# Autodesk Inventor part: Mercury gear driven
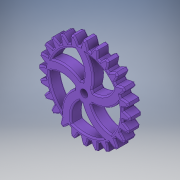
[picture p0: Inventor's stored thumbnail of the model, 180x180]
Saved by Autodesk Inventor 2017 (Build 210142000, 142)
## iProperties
Created: 2016-05
Part Number: Mercury gear driven
Material: Generic
Document SubType Name: Modeling
Designer: Stan
Density: 1 g/cm^3
Appearance: Violet
Author: Stan
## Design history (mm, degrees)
sketch "Sketch1"
  geometry: C1 r 1.984 at (0, 0); A1 r 13.958 centre (21.383, -4.97) between (13.573, -16.538) and (17.096, -18.253); A2 r 13.958 centre (21.383, -4.97) between (13.573, -16.538) and (17.096, -18.253); A3 r 13.958 centre (4.97, -21.383) between (18.253, -17.096) and (16.538, -13.573); A4 r 13.958 centre (4.97, -21.383) between (18.253, -17.096) and (16.538, -13.573); A5 r 13.958 centre (6.387, 21.003) between (-7.26, 23.932) and (-7.536, 20.023); A6 r 13.958 centre (-19.368, 10.335) between (-8.83, 19.488) and (-11.789, 22.056); A7 r 13.958 centre (0.734, 21.94) between (-13.207, 21.238) and (-12.462, 17.391); A8 r 13.958 centre (-21.383, 4.97) between (-13.573, 16.538) and (-17.096, 18.253); A9 r 13.958 centre (-4.97, 21.383) between (-18.253, 17.096) and (-16.538, 13.573); A10 r 13.958 centre (-21.94, -0.734) between (-17.391, 12.462) and (-21.238, 13.207); A11 r 13.958 centre (-10.335, 19.368) between (-22.056, 11.789) and (-19.488, 8.83); A12 r 13.958 centre (-21.003, -6.387) between (-20.023, 7.536) and (-23.932, 7.26); A13 r 13.958 centre (-14.995, 16.033) between (-24.356, 5.679) and (-21.109, 3.485); A14 r 13.958 centre (-18.634, -11.606) between (-21.292, 2.097) and (-24.996, 0.818); A15 r 13.958 centre (-18.634, 11.606) between (-24.996, -0.818) and (-21.292, -2.097); A16 r 13.958 centre (-14.995, -16.033) between (-21.109, -3.485) and (-24.356, -5.679); A17 r 13.958 centre (-21.003, 6.387) between (-23.932, -7.26) and (-20.023, -7.536); A18 r 13.958 centre (-10.335, -19.368) between (-19.488, -8.83) and (-22.056, -11.789); A19 r 13.958 centre (-21.94, 0.734) between (-21.238, -13.207) and (-17.391, -12.462); A20 r 13.958 centre (-4.97, -21.383) between (-16.538, -13.573) and (-18.253, -17.096); A21 r 13.958 centre (-21.383, -4.97) between (-17.096, -18.253) and (-13.573, -16.538); A22 r 13.958 centre (0.734, -21.94) between (-12.462, -17.391) and (-13.207, -21.238); A23 r 13.958 centre (-19.368, -10.335) between (-11.789, -22.056) and (-8.83, -19.488); A24 r 13.958 centre (6.387, -21.003) between (-7.536, -20.023) and (-7.26, -23.932); A25 r 13.958 centre (-16.033, -14.995) between (-5.679, -24.356) and (-3.485, -21.109); A26 r 13.958 centre (11.606, -18.634) between (-2.097, -21.292) and (-0.818, -24.996); A27 r 13.958 centre (-11.606, -18.634) between (0.818, -24.996) and (2.097, -21.292); A28 r 13.958 centre (16.033, -14.995) between (3.485, -21.109) and (5.679, -24.356); A29 r 13.958 centre (-6.387, -21.003) between (7.26, -23.932) and (7.536, -20.023); A30 r 13.958 centre (19.368, -10.335) between (8.83, -19.488) and (11.789, -22.056); A31 r 13.958 centre (-0.734, -21.94) between (13.207, -21.238) and (12.462, -17.391); A32 r 13.958 centre (21.383, -4.97) between (13.573, -16.538) and (17.096, -18.253); A33 r 13.958 centre (4.97, -21.383) between (18.253, -17.096) and (16.538, -13.573); A34 r 13.958 centre (21.94, 0.734) between (17.391, -12.462) and (21.238, -13.207); A35 r 13.958 centre (10.335, -19.368) between (22.056, -11.789) and (19.488, -8.83); A36 r 13.958 centre (21.003, 6.387) between (20.023, -7.536) and (23.932, -7.26); A37 r 13.958 centre (14.995, -16.033) between (24.356, -5.679) and (21.109, -3.485); A38 r 13.958 centre (18.634, 11.606) between (21.292, -2.097) and (24.996, -0.818); A39 r 13.958 centre (18.634, -11.606) between (24.996, 0.818) and (21.292, 2.097); A40 r 13.958 centre (14.995, 16.033) between (21.109, 3.485) and (24.356, 5.679); A41 r 13.958 centre (21.003, -6.387) between (23.932, 7.26) and (20.023, 7.536); A42 r 13.958 centre (10.335, 19.368) between (19.488, 8.83) and (22.056, 11.789); A43 r 13.958 centre (21.94, -0.734) between (21.238, 13.207) and (17.391, 12.462); A44 r 13.958 centre (4.97, 21.383) between (16.538, 13.573) and (18.253, 17.096); A45 r 13.958 centre (21.383, 4.97) between (17.096, 18.253) and (13.573, 16.538); A46 r 13.958 centre (-0.734, 21.94) between (12.462, 17.391) and (13.207, 21.238); A47 r 13.958 centre (19.368, 10.335) between (11.789, 22.056) and (8.83, 19.488); A48 r 13.958 centre (-6.387, 21.003) between (7.536, 20.023) and (7.26, 23.932); A49 r 13.958 centre (16.033, 14.995) between (5.679, 24.356) and (3.485, 21.109); A50 r 13.958 centre (-11.606, 18.634) between (2.097, 21.292) and (0.818, 24.996); A51 r 13.958 centre (11.606, 18.634) between (-0.818, 24.996) and (-2.097, 21.292); A52 r 13.958 centre (-16.033, 14.995) between (-3.485, 21.109) and (-5.679, 24.356); A53 r 13.958 centre (6.387, 21.003) between (-7.26, 23.932) and (-7.536, 20.023); A54 r 13.958 centre (-16.033, 14.995) between (-3.485, 21.109) and (-5.679, 24.356); A55 r 13.958 centre (11.606, 18.634) between (-0.818, 24.996) and (-2.097, 21.292); A56 r 13.958 centre (-11.606, 18.634) between (2.097, 21.292) and (0.818, 24.996); A57 r 13.958 centre (16.033, 14.995) between (5.679, 24.356) and (3.485, 21.109); A58 r 13.958 centre (-6.387, 21.003) between (7.536, 20.023) and (7.26, 23.932); A59 r 13.958 centre (19.368, 10.335) between (11.789, 22.056) and (8.83, 19.488); A60 r 13.958 centre (-0.734, 21.94) between (12.462, 17.391) and (13.207, 21.238); A61 r 13.958 centre (21.383, 4.97) between (17.096, 18.253) and (13.573, 16.538); A62 r 13.958 centre (4.97, 21.383) between (16.538, 13.573) and (18.253, 17.096); A63 r 13.958 centre (21.94, -0.734) between (21.238, 13.207) and (17.391, 12.462); A64 r 13.958 centre (10.335, 19.368) between (19.488, 8.83) and (22.056, 11.789)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; 1 further point
  constraints: 200 point on circle, 101 centre point, 4 horizontal alignment, 4 vertical alignment, 287 other
  dimensions: "d0" = 0 dimension on point (0, 0); "d1" = 0 dimension on point (0, 0); "d2" = 3.96875 diameter of C1
extrude "Extrusion1" new body sketch "Sketch1" distance "d3" = 6.35; taper "d4" = 0 deg
sketch "Sketch3"
  geometry: A1 r 12.294 centre (-12.542, 8.845) between (-0.748, 5.374) and (-4.929, 18.499); A2 r 17.433 centre (-12.542, 8.845) between (4.077, 3.58) and (1.571, 19.08); A3 r 12.294 centre (-12.288, -9.195) between (-5.342, 0.949) and (-19.117, 1.029); A4 r 17.433 centre (-12.288, -9.195) between (-2.145, 4.984) and (-17.66, 7.39); A5 r 12.294 centre (4.948, -14.528) between (-2.554, -4.787) and (-6.886, -17.863); A6 r 17.433 centre (4.948, -14.528) between (-5.403, -0.5) and (-12.486, -14.513); A7 r 12.294 centre (15.346, 0.216) between (3.764, -3.908) and (14.861, -12.069); A8 r 17.433 centre (15.346, 0.216) between (-1.194, -5.293) and (9.944, -16.359); A9 r 12.294 centre (4.537, 14.662) between (4.88, 2.372) and (16.07, 10.404); A10 r 17.433 centre (4.537, 14.662) between (4.665, -2.771) and (18.631, 4.402); A11 r 19.144 centre (0, 0) between (16.07, 10.404) and (1.571, 19.08); A12 r 19.144 centre (0, 0) between (14.861, -12.069) and (18.631, 4.402); A13 r 19.144 centre (0, 0) between (-6.886, -17.863) and (9.944, -16.359); A14 r 19.144 centre (0, 0) between (-4.929, 18.499) and (-17.66, 7.39); A15 r 19.144 centre (0, 0) between (-19.117, 1.029) and (-12.486, -14.513); A16 r 5.426 centre (0, 0) between (-0.748, 5.374) and (-2.145, 4.984); A17 r 5.426 centre (0, 0) between (4.88, 2.372) and (4.077, 3.58); A18 r 5.426 centre (0, 0) between (3.764, -3.908) and (4.665, -2.771); A19 r 5.426 centre (0, 0) between (-5.342, 0.949) and (-5.403, -0.5); A20 r 5.426 centre (0, 0) between (-2.554, -4.787) and (-1.194, -5.293); 1 further point
  constraints: 40 point on circle, 20 centre point, 2 coincident, 36 other
  dimensions: "d17" = 360 deg dimension on point (0, 0) A1.centre (derived)
extrude "Extrusion3" cut sketch "Sketch3" distance "d19" = 6.35; taper "d20" = 0 deg
fillet "Fillet1" dims "d21" = 0.79375
fillet "Fillet3" dims "d26" = 0.762
fillet "Fillet4" dims "d27" = 0.762
fillet "Fillet5" dims "d28" = 0.79375
body "Solid1"
